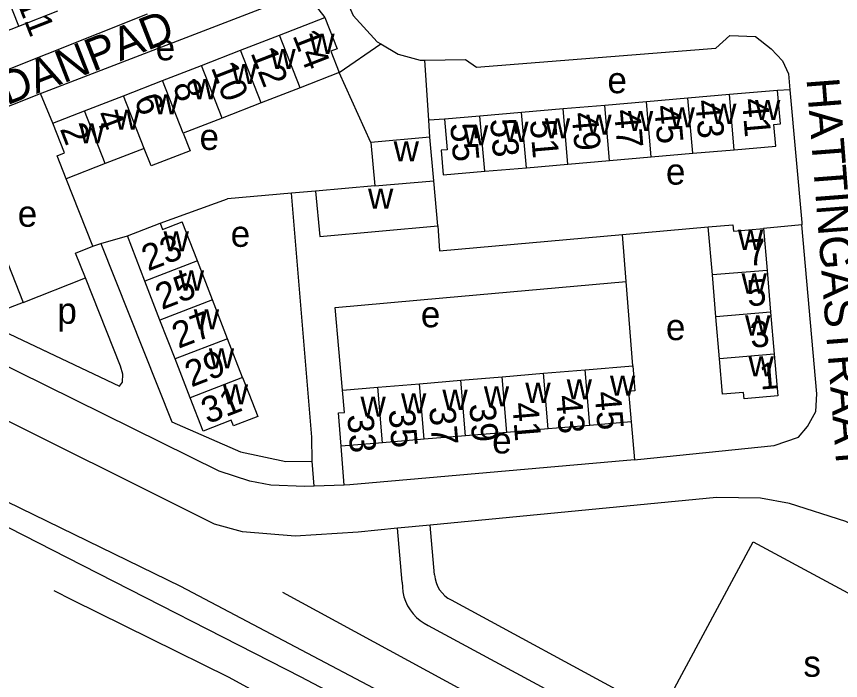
# Model space of a CAD drawing. Extents: x 163026 to 166241, y 382475 to 384501.
# Drawn here: x 164035.2 to 164160.9, y 383738.3 to 383839.7 of the extents above; entities that cross this region are included whole.
import ezdxf

# ---------------------------------------------------------------- set-up
doc = ezdxf.new("R2010")
doc.units = 0
for name, color, linetype in [('BLT_Basislijn', 7, 'Continuous'), ('BLT_Bebouwing', 7, 'Continuous'), ('BLT_Centroide', 7, 'Continuous'), ('BLT_Huisnummer', 7, 'Continuous'), ('BLT_Huisnummer_ tussenligend', 7, 'Continuous'), ('BLT_Onderverdeling_panden', 7, 'Continuous'), ('BLT_Spoorlijn', 7, 'Continuous'), ('BLT_Straatnaam', 7, 'Continuous')]:
    doc.layers.add(name, color=color, linetype=linetype)

msp = doc.modelspace()

# ---------------------------------------------------------------- linework, layer by layer
at = {"layer": 'BLT_Basislijn'}
for p, q in [((164008.17, 383821.42), (164055.16, 383840.09)), ((164084.4, 383831.13), (164090.76, 383835.53)), ((164098.1, 383823.87), (164097.47, 383833.04)), ((164089.25, 383820.48), (164084.4, 383831.13)), ((164040.73, 383823.4), (164038.85, 383827.92)), ((164153.21, 383828.51), (164151.34, 383828.41)), ((164100.48, 383824.01), (164098.1, 383823.87)), ((164098.27, 383821.28), (164098.1, 383823.87)), ((164046.83, 383804.6), (164042.74, 383814.93)), ((164077.14, 383812.7), (164067.38, 383811.84)), ((164080.83, 383813.03), (164077.14, 383812.7)), ((164057.1, 383808.13), (164067.38, 383811.84)), ((164099.48, 383807.72), (164099.74, 383803.89)), ((164127.66, 383806.4), (164140.76, 383807.58)), ((164155.04, 383807.86), (164149.2, 383807.31)), ((164048.02, 383805.01), (164052.09, 383806.2)), ((164099.74, 383803.89), (164127.66, 383806.4)), ((164128.22, 383799.24), (164127.66, 383806.4)), ((164046.83, 383804.6), (164047.41, 383804.83)), ((164047.41, 383804.83), (164048.02, 383805.01)), ((164044.19, 383803.55), (164046.83, 383804.6)), ((164045.68, 383799.79), (164044.19, 383803.55)), ((164036.17, 383796.02), (164045.68, 383799.79)), ((164100.24, 383796.73), (164128.22, 383799.24)), ((164129.22, 383786.35), (164128.22, 383799.24)), ((164128.99, 383777.78), (164129.5, 383771.99)), ((164085.18, 383768.12), (164084.73, 383774.05)), ((164080.61, 383767.98), (164080.32, 383771.76)), ((164085.18, 383768.12), (164080.61, 383767.98)), ((164098.31, 383762.01), (164093.33, 383761.53)), ((164098.99, 383754.43), (164098.31, 383762.01)), ((164094.05, 383753.3), (164093.33, 383761.53)), ((164075.75, 383751.78), (164107.18, 383734.72)), ((164101.51, 383750.58), (164148.19, 383725.34)), ((164098.02, 383746.69), (164163.74, 383711.24))]:
    msp.add_line(p, q, dxfattribs=at)
for points in [[(164051.58, 383896.12), (164053.16, 383899.93), (164054.69, 383900.37), (164058.61, 383900.65), (164061.96, 383899.38), (164065.05, 383896.1), (164065.14, 383895.3), (164064.32, 383893.01), (164064.65, 383890.88), (164081.89, 383846.79), (164082.46, 383845.87), (164084.59, 383844.4), (164086.56, 383839.84), (164090.22, 383835.85), (164090.76, 383835.53)], [(164487.56, 383450.47), (164485.27, 383453.7), (164461.77, 383475.44), (164415.36, 383515.97), (164364.92, 383557.15), (164327.9, 383585.54), (164282.31, 383618.56), (164259.41, 383634.23), (164211.65, 383666.06), (164167.61, 383692.96), (164167.28, 383695.05), (164154.4, 383702.67), (164152.43, 383702), (164109.02, 383726.87), (164060.25, 383752.65), (163978.72, 383792.41), (163915.23, 383819.71), (163854.36, 383843.93), (163797.39, 383864.74), (163783.25, 383869.74), (163782.14, 383872.57), (163761.29, 383879.43), (163759.17, 383880.76)], [(164093.33, 383761.53), (164087.31, 383760.95), (164077.71, 383760.31), (164069.67, 383760.97), (164065.4, 383762.14), (163952.55, 383818.5), (163947.43, 383822.83), (163943.53, 383828.01), (163938.56, 383826.71), (163933.79, 383838.65), (163933.74, 383839.42), (163938.95, 383841.81), (163938.52, 383843.44), (163935.91, 383845.72), (163934.7, 383846.07), (163931.51, 383845.91), (163925.68, 383842.56), (163923.54, 383841.83), (163919.44, 383841.28), (163915.65, 383841.27), (163911.75, 383841.92), (163907.2, 383844.22), (163903.36, 383847.84), (163901.99, 383849.94)], [(164038.85, 383827.92), (164078.91, 383843.41), (164079.61, 383843.15), (164080.03, 383842.4), (164082.24, 383839.54)], [(164097.47, 383833.04), (164103.71, 383833.11), (164105.37, 383831.97), (164141.93, 383834.87), (164144.02, 383836.78), (164147.98, 383836.66), (164150.33, 383834.78), (164152.06, 383832.92), (164153.01, 383830.93), (164153.21, 383828.51)], [(164090.76, 383835.53), (164093.41, 383833.95), (164096.79, 383833.03), (164097.47, 383833.04)], [(164017.78, 383819.83), (164026.1, 383822.91), (164038.85, 383827.92)], [(164153.21, 383828.51), (164155.01, 383808.22), (164155.04, 383807.86)], [(164080.32, 383771.76), (164080.23, 383775.45), (164077.14, 383812.7)], [(164080.61, 383767.98), (164079.14, 383767.94), (164073.97, 383768.14), (164070.79, 383768.74), (164066.11, 383770.28), (164000.07, 383802.89), (163985.19, 383810.56)], [(164129.5, 383771.99), (164129.95, 383772.03), (164150.79, 383774.17), (164154.54, 383775.47), (164155.89, 383777.1), (164157.15, 383779.36), (164157.31, 383782.09), (164155.04, 383807.86)], [(164048.02, 383805.01), (164058.9, 383777.8), (164069.35, 383773.21), (164076.3, 383771.73), (164080.32, 383771.76)], [(164028.12, 383794.02), (164050.87, 383783.22), (164051.34, 383783.85), (164051.4, 383785.05), (164051.03, 383786.31), (164045.68, 383799.79)], [(164084.95, 383782.62), (164083.8, 383795.26), (164100.24, 383796.73)], [(164129.5, 383771.99), (164086.05, 383768.15), (164085.18, 383768.12)], [(164222.12, 383735.52), (164216.01, 383736.15), (164207.67, 383738.82), (164161.77, 383762.57), (164153.13, 383765.33), (164148.71, 383766.15), (164142.02, 383766.23), (164098.31, 383762.01)], [(164149.55, 383727.87), (164134.87, 383735.78), (164147.61, 383759.44), (164181.7, 383741.08), (164168.96, 383717.41), (164153.96, 383725.49)], [(164098.99, 383754.43), (164099.07, 383753.83), (164099.22, 383753.24), (164099.45, 383752.68), (164099.75, 383752.15), (164100.12, 383751.67), (164100.54, 383751.23), (164101.02, 383750.86), (164101.51, 383750.58)], [(164094.05, 383753.3), (164094.06, 383752.55), (164094.14, 383751.81), (164094.31, 383751.08), (164094.55, 383750.38), (164094.87, 383749.7), (164095.25, 383749.06), (164095.71, 383748.47), (164096.22, 383747.93), (164096.79, 383747.44), (164097.41, 383747.02), (164098.02, 383746.69)]]:
    msp.add_lwpolyline(points, dxfattribs=at)
at = {"layer": 'BLT_Bebouwing'}
for p, q in [((164035.54, 383838.25), (164041.46, 383840.58)), ((164075.33, 383836.85), (164082.24, 383839.54)), ((164029.61, 383835.93), (164035.54, 383838.25)), ((164069.38, 383834.54), (164075.33, 383836.85)), ((164063.42, 383832.23), (164069.38, 383834.54)), ((164057.47, 383829.91), (164063.42, 383832.23)), ((164084.4, 383831.13), (164078.45, 383828.82)), ((164051.52, 383827.6), (164057.47, 383829.91)), ((164078.45, 383828.82), (164072.5, 383826.51)), ((164045.57, 383825.28), (164051.52, 383827.6)), ((164143.99, 383827.78), (164137.65, 383827.23)), ((164151.34, 383828.41), (164143.99, 383827.78)), ((164072.5, 383826.51), (164066.55, 383824.19)), ((164124.95, 383826.13), (164118.61, 383825.58)), ((164131.3, 383826.68), (164124.95, 383826.13)), ((164137.65, 383827.23), (164131.3, 383826.68)), ((164040.73, 383823.4), (164045.57, 383825.28)), ((164112.26, 383825.03), (164105.91, 383824.48)), ((164118.61, 383825.58), (164112.26, 383825.03)), ((164066.55, 383824.19), (164060.6, 383821.88)), ((164105.91, 383824.48), (164100.48, 383824.01)), ((164098.27, 383821.28), (164089.25, 383820.48)), ((164098.87, 383814.59), (164098.27, 383821.28)), ((164089.25, 383820.48), (164089.84, 383813.83)), ((164054.64, 383819.56), (164048.69, 383817.25)), ((164132.03, 383818.26), (164138.38, 383818.81)), ((164138.38, 383818.81), (164144.72, 383819.36)), ((164119.33, 383817.16), (164125.68, 383817.71)), ((164125.68, 383817.71), (164132.03, 383818.26)), ((164048.69, 383817.25), (164042.74, 383814.93)), ((164100.29, 383815.51), (164106.64, 383816.06)), ((164106.64, 383816.06), (164112.99, 383816.61)), ((164112.99, 383816.61), (164119.33, 383817.16)), ((164089.84, 383813.83), (164080.83, 383813.03)), ((164099.48, 383807.72), (164098.87, 383814.59)), ((164080.83, 383813.03), (164081.45, 383806.12)), ((164052.09, 383806.2), (164057.1, 383808.13)), ((164062.78, 383802.38), (164060.48, 383808.32)), ((164081.45, 383806.12), (164099.48, 383807.72)), ((164141.38, 383800.22), (164140.76, 383807.58)), ((164149.2, 383807.31), (164149.74, 383800.92)), ((164054.77, 383799.28), (164052.09, 383806.2)), ((164065.09, 383796.44), (164062.78, 383802.38)), ((164033.86, 383801.97), (164036.17, 383796.02)), ((164149.74, 383800.92), (164150.27, 383794.52)), ((164141.92, 383793.82), (164141.38, 383800.22)), ((164057.07, 383793.33), (164054.77, 383799.28)), ((164067.39, 383790.49), (164065.09, 383796.44)), ((164142.45, 383787.43), (164141.92, 383793.82)), ((164150.27, 383794.52), (164150.81, 383788.13)), ((164059.37, 383787.39), (164057.07, 383793.33)), ((164069.69, 383784.55), (164067.39, 383790.49)), ((164061.67, 383781.45), (164059.37, 383787.39)), ((164121.95, 383785.74), (164129.22, 383786.35)), ((164102.98, 383784.14), (164109.31, 383784.68)), ((164109.31, 383784.68), (164115.63, 383785.21)), ((164115.63, 383785.21), (164121.95, 383785.74)), ((164090.34, 383783.08), (164096.66, 383783.61)), ((164096.66, 383783.61), (164102.98, 383784.14)), ((164084.95, 383782.62), (164090.34, 383783.08)), ((164122.67, 383777.25), (164116.34, 383776.71)), ((164128.99, 383777.78), (164122.67, 383777.25)), ((164110.02, 383776.18), (164103.7, 383775.65)), ((164116.34, 383776.71), (164110.02, 383776.18)), ((164091.05, 383774.58), (164084.73, 383774.05)), ((164097.38, 383775.12), (164091.05, 383774.58)), ((164103.7, 383775.65), (164097.38, 383775.12))]:
    msp.add_line(p, q, dxfattribs=at)
for points in [[(164082.24, 383839.54), (164084.09, 383834.78), (164083.13, 383834.41), (164084.4, 383831.13)], [(164144.72, 383819.36), (164151.07, 383819.91), (164150.78, 383823.2), (164151.79, 383823.29), (164151.34, 383828.41)], [(164100.48, 383824.01), (164100.88, 383819.36), (164099.97, 383819.28), (164100.29, 383815.51)], [(164042.74, 383814.93), (164041.37, 383818.44), (164042.49, 383818.88), (164040.73, 383823.4)], [(164060.6, 383821.88), (164061.66, 383819.19), (164055.75, 383816.9), (164054.64, 383819.56)], [(164057.1, 383808.13), (164057.47, 383807.16), (164060.48, 383808.32)], [(164140.76, 383807.58), (164144.51, 383807.89), (164144.59, 383806.92), (164149.2, 383807.31)], [(164036.17, 383796.02), (164032.6, 383794.63), (164032.23, 383795.61), (164028.12, 383794.02)], [(164150.81, 383788.13), (164151.35, 383781.74), (164146.22, 383781.31), (164146.14, 383782.29), (164142.91, 383782.02), (164142.45, 383787.43)], [(164129.22, 383786.35), (164129.54, 383782.51), (164128.59, 383782.43), (164128.99, 383777.78)], [(164069.69, 383784.55), (164070.18, 383783.27), (164071.99, 383778.61), (164068.29, 383777.18), (164067.96, 383778.04), (164063.64, 383776.37), (164061.67, 383781.45)], [(164084.73, 383774.05), (164084.3, 383779.17), (164085.23, 383779.24), (164084.95, 383782.62)]]:
    msp.add_lwpolyline(points, dxfattribs=at)
at = {"layer": 'BLT_Onderverdeling_panden'}
for p, q in [((164035.54, 383838.25), (164032.42, 383846.18)), ((164078.45, 383828.82), (164075.33, 383836.85)), ((164072.5, 383826.51), (164069.38, 383834.54)), ((164066.55, 383824.19), (164063.42, 383832.23)), ((164060.6, 383821.88), (164057.47, 383829.91)), ((164054.64, 383819.56), (164051.52, 383827.6)), ((164144.72, 383819.36), (164143.99, 383827.78)), ((164125.68, 383817.71), (164124.95, 383826.13)), ((164132.03, 383818.26), (164131.3, 383826.68)), ((164138.38, 383818.81), (164137.65, 383827.23)), ((164048.69, 383817.25), (164045.57, 383825.28)), ((164112.99, 383816.61), (164112.26, 383825.03)), ((164119.33, 383817.16), (164118.61, 383825.58)), ((164106.64, 383816.06), (164105.91, 383824.48)), ((164089.84, 383813.83), (164098.87, 383814.59)), ((164062.78, 383802.38), (164054.77, 383799.28)), ((164149.74, 383800.92), (164141.38, 383800.22)), ((164065.09, 383796.44), (164057.07, 383793.33)), ((164150.27, 383794.52), (164141.92, 383793.82)), ((164067.39, 383790.49), (164059.37, 383787.39)), ((164150.81, 383788.13), (164142.45, 383787.43)), ((164110.02, 383776.18), (164109.31, 383784.68)), ((164116.34, 383776.71), (164115.63, 383785.21)), ((164122.67, 383777.25), (164121.95, 383785.74)), ((164069.69, 383784.55), (164061.67, 383781.45)), ((164097.38, 383775.12), (164096.66, 383783.61)), ((164103.7, 383775.65), (164102.98, 383784.14)), ((164091.05, 383774.58), (164090.34, 383783.08))]:
    msp.add_line(p, q, dxfattribs=at)
at = {"layer": 'BLT_Spoorlijn'}
for points in [[(164236.28, 383645.06), (164219.39, 383655.93), (164201.88, 383667.38), (164171.24, 383685.91), (164141.27, 383704.11), (164108.61, 383722.98), (164078.64, 383738.81), (164042.94, 383757.01), (164013.98, 383771.83), (163987.72, 383784.3), (163962.46, 383795.42), (163948.73, 383801.48), (163934.26, 383807.96)], [(164040.87, 383752.01), (164043.68, 383750.6), (164067.59, 383738.81), (164082.6, 383730.6)]]:
    msp.add_lwpolyline(points, dxfattribs=at)

# ---------------------------------------------------------------- texts
at = {"layer": 'BLT_Centroide'}
for s, p in [('e', (164056.41, 383833.01)), ('w', (164079.86, 383834)), ('w', (164073.91, 383831.69)), ('w', (164067.97, 383829.38)), ('e', (164125.36, 383827.98)), ('w', (164062.02, 383827.06)), ('w', (164056.06, 383824.75)), ('w', (164141.19, 383823.3)), ('w', (164147.89, 383823.88)), ('w', (164050.11, 383822.42)), ('w', (164128.48, 383822.19)), ('w', (164134.84, 383822.75)), ('w', (164109.45, 383820.55)), ('w', (164115.8, 383821.09)), ('w', (164122.14, 383821.64)), ('w', (164044.72, 383820.31)), ('e', (164063.11, 383819.32)), ('w', (164103.3, 383820.02)), ('w', (164092.73, 383817.56)), ('e', (164134.29, 383814.02)), ('w', (164088.82, 383810.34)), ('e', (164035.36, 383807.59)), ('e', (164067.86, 383804.52)), ('w', (164057.62, 383803.81)), ('w', (164145.27, 383804.06)), ('w', (164059.93, 383797.84)), ('w', (164145.83, 383797.38)), ('p', (164041.41, 383792.77)), ('w', (164062.23, 383791.91)), ('e', (164096.89, 383792.23)), ('e', (164134.29, 383790.27)), ('w', (164146.37, 383790.97)), ('w', (164064.53, 383785.97)), ('w', (164146.89, 383784.72)), ('w', (164125.75, 383781.78)), ('w', (164066.66, 383780.47)), ('w', (164112.83, 383780.69)), ('w', (164119.14, 383781.22)), ('w', (164093.86, 383779.09)), ('w', (164100.17, 383779.62)), ('w', (164106.5, 383780.16)), ('w', (164087.67, 383778.58)), ('e', (164107.77, 383772.96)), ('s', (164155.27, 383738.86))]:
    msp.add_text(s, height=4, dxfattribs=at).set_placement(p)
at = {"layer": 'BLT_Huisnummer'}
for s, rotation, p in [('14', 291.2495, (164077.26, 383836.8)), ('10', 291.2447, (164064.81, 383831.93)), ('6', 291.2509, (164053.07, 383827.04)), ('41', 274.9451, (164145.87, 383827.08)), ('49', 274.9421, (164119.89, 383824.96)), ('45', 274.9433, (164132.49, 383826.04)), ('2', 291.2505, (164041.75, 383822.54)), ('55', 274.9437, (164101.35, 383823.31)), ('23', 21.1663, (164055.24, 383800.75)), ('7', 4.7948, (164146.79, 383801.59)), ('27', 21.1663, (164059.88, 383788.93)), ('1', 4.7951, (164148.68, 383782.71)), ('31', 21.1743, (164064.34, 383777.42)), ('45', 274.8133, (164123.4, 383782.32)), ('37', 274.8128, (164098.14, 383780.01)), ('41', 274.8133, (164110.81, 383780.64)), ('33', 274.8155, (164085.64, 383778.84))]:
    msp.add_text(s, height=4, rotation=rotation, dxfattribs=at).set_placement(p)
at = {"layer": 'BLT_Huisnummer_ tussenligend'}
for s, rotation, p in [('11', 291.4253, (164035.2, 383841.9)), ('12', 291.2447, (164070.85, 383834.16)), ('8', 291.2509, (164058.96, 383829.14)), ('43', 274.9451, (164138.74, 383826.86)), ('4', 291.2505, (164047.08, 383824.66)), ('47', 274.9433, (164126.36, 383825.38)), ('53', 274.9421, (164107.44, 383824)), ('51', 274.9421, (164113.51, 383823.84)), ('25', 21.1663, (164057.34, 383794.85)), ('5', 4.7951, (164146.79, 383795.42)), ('3', 4.7951, (164147.27, 383789.09)), ('29', 21.1663, (164061.85, 383783.03)), ('43', 274.8133, (164117.48, 383781.76)), ('35', 274.8155, (164091.96, 383779.61)), ('39', 274.8128, (164104.27, 383780.48))]:
    msp.add_text(s, height=4, rotation=rotation, dxfattribs=at).set_placement(p)
at = {"layer": 'BLT_Straatnaam'}
for s, height, rotation, p in [('ADANPAD', 5, 21.3072, (164029.52, 383824.47)), ('HATTINGASTRAAT', 4.9999, 274.4155, (164155.74, 383830.17))]:
    msp.add_text(s, height=height, rotation=rotation, dxfattribs=at).set_placement(p)

doc.saveas('drawing.dxf')
